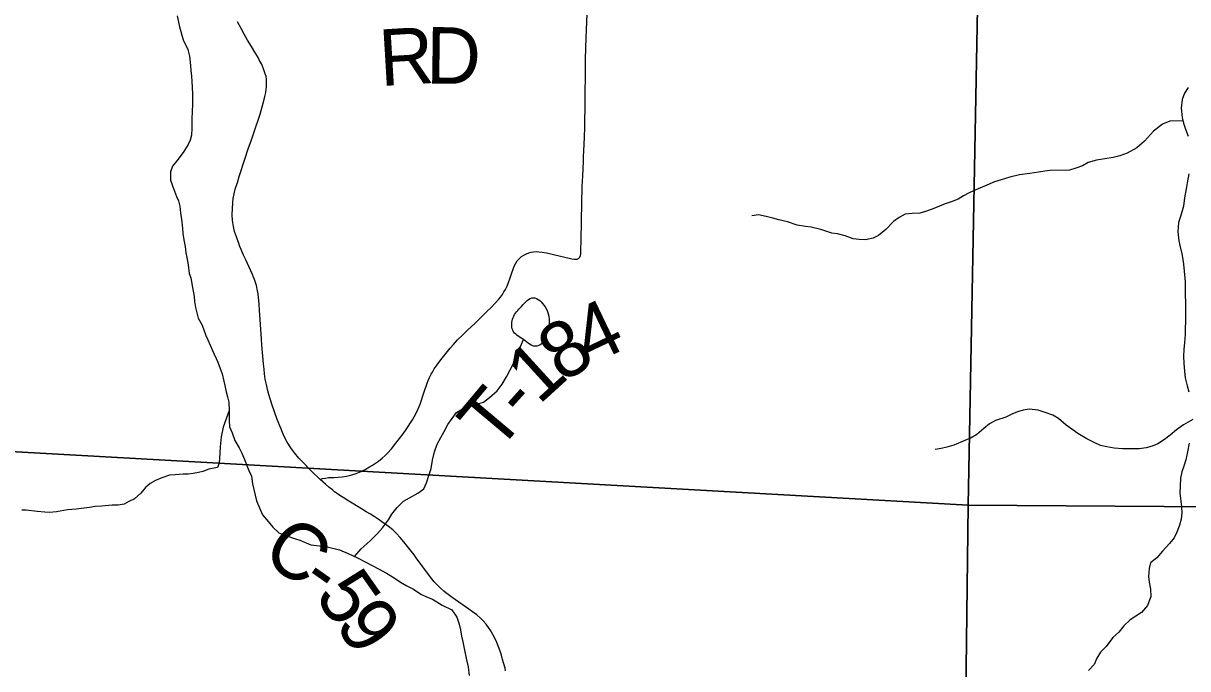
# Model space of a CAD drawing. Extents: x 0 to 34, y 0 to 22.
# Drawn here: x 14.532 to 15.702, y 16.764 to 17.412 of the extents above; entities that cross this region are included whole.
import ezdxf

# ---------------------------------------------------------------- set-up
doc = ezdxf.new("R2010")
doc.units = 0
for name, color, linetype in [('GM_X_Corporation', 7, 'Continuous'), ('GM_X_County_Road', 7, 'Continuous'), ('GM_X_County_Road_Text', 7, 'Continuous'), ('GM_X_Minor_River', 7, 'Continuous'), ('GM_X_Township_Road', 7, 'Continuous'), ('GM_X_Township_Road_Text', 7, 'Continuous')]:
    doc.layers.add(name, color=color, linetype=linetype)

msp = doc.modelspace()

# ---------------------------------------------------------------- linework, layer by layer
at = {"layer": 'GM_X_Corporation'}
for points in [[(14.4926, 17.9788), (15.5004, 17.9447), (15.4816, 16.9282), (14.4709, 16.9847)], [(15.5004, 17.9447), (16.4906, 17.9114), (16.466, 16.9263), (16.466, 16.9214), (15.4816, 16.9282)], [(14.4709, 16.9847), (15.4816, 16.9282), (15.4691, 15.9163), (14.4583, 15.9623)], [(15.4816, 16.9282), (16.466, 16.9214), (16.4563, 15.9084), (15.4691, 15.9163)]]:
    msp.add_lwpolyline(points, close=True, dxfattribs=at)
at = {"layer": 'GM_X_County_Road'}
msp.add_lwpolyline([(15.0166, 16.7617), (15.0161, 16.7642), (15.0148, 16.7687), (15.0136, 16.773), (15.0124, 16.7773), (15.0111, 16.7813), (15.0095, 16.7856), (15.0077, 16.7901), (15.0061, 16.7937), (15.004, 16.7979), (15.0018, 16.8016), (14.9994, 16.8052), (14.997, 16.8085), (14.9942, 16.8117), (14.9914, 16.8146), (14.9878, 16.8177), (14.9835, 16.8209), (14.9797, 16.8236), (14.9629, 16.8353), (14.9589, 16.8381), (14.9566, 16.84), (14.9545, 16.8416), (14.9508, 16.8449), (14.9474, 16.8482), (14.9449, 16.851), (14.9424, 16.8539), (14.9401, 16.857), (14.9269, 16.8751), (14.9248, 16.8781), (14.918, 16.8865), (14.9143, 16.8912), (14.9107, 16.8956), (14.907, 16.8995), (14.9032, 16.9031), (14.8991, 16.9065), (14.8958, 16.9089), (14.8923, 16.9114), (14.8886, 16.914), (14.8847, 16.9166), (14.881, 16.919), (14.8767, 16.9215), (14.8718, 16.9244), (14.8593, 16.9321), (14.8534, 16.9357), (14.8501, 16.9379), (14.8479, 16.9394), (14.8448, 16.9416), (14.8426, 16.9433), (14.8392, 16.9461), (14.8357, 16.9491), (14.8304, 16.954), (14.828, 16.9561), (14.8244, 16.9595), (14.8207, 16.9632), (14.8134, 16.971), (14.8088, 16.9754), (14.8044, 16.9805), (14.8007, 16.9855), (14.7971, 16.9914), (14.7944, 16.9965), (14.7925, 17.0011), (14.7907, 17.0053), (14.7872, 17.0141), (14.7818, 17.0295), (14.7786, 17.0393), (14.7774, 17.0443), (14.7763, 17.0492), (14.7752, 17.0548), (14.7744, 17.0599), (14.7739, 17.0646), (14.7734, 17.0702), (14.7717, 17.0893), (14.7713, 17.0951), (14.7693, 17.1239), (14.7691, 17.1302), (14.7688, 17.1338), (14.7684, 17.1367), (14.7679, 17.1405), (14.7673, 17.1436), (14.7662, 17.1489), (14.7653, 17.1518), (14.7643, 17.1548), (14.7632, 17.1573), (14.7622, 17.16), (14.7555, 17.1745), (14.7534, 17.1794), (14.751, 17.1849), (14.7497, 17.1879), (14.7485, 17.1912), (14.7462, 17.1979), (14.7444, 17.203), (14.7433, 17.208), (14.7424, 17.2141), (14.7419, 17.2199), (14.7425, 17.2323), (14.743, 17.2363), (14.7438, 17.2409), (14.745, 17.2457), (14.7471, 17.2525), (14.749, 17.2585), (14.7545, 17.2757), (14.7579, 17.2861), (14.7612, 17.2953), (14.7642, 17.3043), (14.77, 17.3211), (14.773, 17.3321), (14.7737, 17.3345), (14.7747, 17.3387), (14.7756, 17.3427), (14.7762, 17.346), (14.7763, 17.348), (14.7765, 17.3506), (14.7763, 17.3562), (14.7759, 17.3588), (14.7752, 17.3616), (14.7745, 17.3637), (14.7735, 17.3666), (14.7725, 17.3694), (14.7714, 17.3715), (14.7695, 17.375), (14.7679, 17.3781), (14.7647, 17.3833), (14.7612, 17.3889), (14.7574, 17.3953), (14.7541, 17.4013), (14.7509, 17.4072), (14.7472, 17.4139)], dxfattribs=at)
at = {"layer": 'GM_X_Minor_River'}
for points in [[(14.6867, 17.4199), (14.689, 17.4089), (14.6928, 17.3956), (14.6974, 17.3861), (14.6989, 17.3793), (14.7001, 17.3698), (14.7005, 17.3648), (14.7009, 17.3591), (14.7013, 17.3538), (14.7017, 17.3481), (14.7021, 17.3409), (14.7021, 17.331), (14.7014, 17.3162), (14.7015, 17.3067), (14.7011, 17.2999), (14.6996, 17.295), (14.6977, 17.2904), (14.6928, 17.2824), (14.6864, 17.274), (14.6819, 17.2687), (14.68, 17.263), (14.68, 17.2547), (14.6831, 17.2463), (14.6861, 17.2384), (14.6881, 17.2338), (14.6892, 17.2285), (14.69, 17.2217)], [(15.7025, 17.3478), (15.6988, 17.3421), (15.6966, 17.3356), (15.6956, 17.3272), (15.6965, 17.3177), (15.6978, 17.312), (15.6998, 17.306), (15.7025, 17.2988)], [(15.6973, 17.3143), (15.6841, 17.3141), (15.6769, 17.3109), (15.6676, 17.3039), (15.6587, 17.2939), (15.6508, 17.2873), (15.6414, 17.2818), (15.6339, 17.279), (15.6271, 17.2774), (15.6105, 17.2748), (15.6022, 17.2724), (15.5962, 17.2692), (15.5898, 17.2669), (15.5834, 17.2648), (15.564, 17.2645), (15.5584, 17.2637), (15.5523, 17.2628), (15.5436, 17.2615), (15.533, 17.2602), (15.5232, 17.2577), (15.5145, 17.2549), (15.5081, 17.2529), (15.498, 17.2485), (15.4893, 17.245), (15.4825, 17.2418), (15.4769, 17.2391), (15.4713, 17.2355), (15.4653, 17.2332), (15.4585, 17.2308), (15.4528, 17.2284), (15.4453, 17.2256), (15.4385, 17.2232), (15.4329, 17.2216), (15.4253, 17.2211), (15.4181, 17.2206), (15.4121, 17.217), (15.4065, 17.2132), (15.3986, 17.205), (15.3915, 17.1992), (15.3859, 17.1965), (15.3783, 17.1948), (15.3719, 17.1951), (15.3658, 17.1957), (15.3578, 17.1986), (15.3502, 17.2008), (15.3445, 17.2014), (15.3334, 17.205), (15.3236, 17.2075), (15.3179, 17.2082), (15.3095, 17.2096), (15.3, 17.2128), (15.2912, 17.2149), (15.2851, 17.2164), (15.2786, 17.2182), (15.2707, 17.2199), (15.2642, 17.2187)], [(15.7032, 17.2612), (15.7014, 17.2521), (15.7004, 17.246), (15.6987, 17.2368), (15.6977, 17.2285), (15.6948, 17.2182), (15.6927, 17.212), (15.6921, 17.2029), (15.6933, 17.1938), (15.6946, 17.1878), (15.6962, 17.1806), (15.6975, 17.173), (15.6983, 17.1669), (15.6994, 17.1525), (15.6999, 17.1187), (15.6995, 17.0997), (15.6989, 17.0914), (15.6982, 17.0845), (15.698, 17.0777), (15.6981, 17.0708), (15.699, 17.0625), (15.6995, 17.056), (15.7015, 17.0481), (15.7031, 17.042)], [(14.69, 17.2217), (14.6912, 17.2129), (14.692, 17.2061), (14.6923, 17.2012), (14.6935, 17.1947), (14.6947, 17.1879), (14.6955, 17.1818), (14.6962, 17.1769), (14.6978, 17.1696), (14.6986, 17.1609), (14.7005, 17.1564), (14.702, 17.1469), (14.7036, 17.1378), (14.704, 17.1328), (14.7051, 17.1267), (14.7063, 17.1214), (14.7078, 17.1161), (14.7117, 17.1089), (14.7155, 17.0987), (14.7174, 17.0941), (14.722, 17.0835), (14.7274, 17.0717), (14.73, 17.0653), (14.7319, 17.06), (14.7335, 17.0528), (14.7346, 17.0482), (14.7358, 17.0418), (14.7373, 17.0368), (14.7385, 17.0315), (14.7389, 17.0232), (14.7389, 17.0133), (14.7393, 17.0068), (14.742, 17.0008), (14.7447, 16.9932), (14.7489, 16.9856), (14.7516, 16.9803), (14.7543, 16.9738), (14.7585, 16.9628), (14.7612, 16.9571), (14.7623, 16.9495), (14.7662, 16.9324), (14.7692, 16.9252), (14.7723, 16.9184), (14.778, 16.9116), (14.7826, 16.9059), (14.7887, 16.9002), (14.7948, 16.8979), (14.8054, 16.8942), (14.81, 16.893)], [(14.8649, 16.8766), (14.8716, 16.884), (14.8805, 16.8922), (14.888, 16.8995), (14.8928, 16.9053), (14.8991, 16.9134), (14.9024, 16.9191), (14.9076, 16.9257), (14.914, 16.9322), (14.92, 16.9354), (14.9286, 16.9401), (14.9346, 16.9444), (14.9371, 16.9505), (14.94, 16.9589), (14.9418, 16.965), (14.9432, 16.9734), (14.9453, 16.9818), (14.9479, 16.9894), (14.9515, 16.9959), (14.9548, 17.0021), (14.9585, 17.009), (14.9674, 17.0213), (14.9734, 17.0248), (14.9813, 17.0276), (14.9873, 17.0296), (14.9945, 17.0316), (15.0005, 17.0363), (15.0083, 17.0429), (15.0132, 17.0498), (15.0176, 17.0571), (15.0213, 17.064), (15.0246, 17.0705), (15.0271, 17.0763), (15.0348, 17.0946)], [(14.7389, 17.0232), (14.7329, 17.0064), (14.7307, 16.9966), (14.7299, 16.9867), (14.7296, 16.9802), (14.7288, 16.9704), (14.727, 16.9658), (14.7186, 16.9643), (14.7125, 16.962), (14.708, 16.9608), (14.7027, 16.9597), (14.6978, 16.9593), (14.6928, 16.9593), (14.6845, 16.9585), (14.6788, 16.9581), (14.6712, 16.9554), (14.6647, 16.9528), (14.6594, 16.9497), (14.6549, 16.9459), (14.65, 16.9402), (14.6439, 16.9345), (14.6382, 16.9318), (14.6333, 16.9292), (14.6272, 16.928), (14.6212, 16.928), (14.6109, 16.9272), (14.6041, 16.9268), (14.5984, 16.9257), (14.5851, 16.9241), (14.5764, 16.9234), (14.5654, 16.9214), (14.5582, 16.9207), (14.5536, 16.921), (14.546, 16.9218), (14.535, 16.9229), (14.5304, 16.9229)], [(15.7072, 17.014), (15.698, 17.0089), (15.6909, 17.0038), (15.6845, 16.9984), (15.6789, 16.9941), (15.6722, 16.9898), (15.6662, 16.9875), (15.6605, 16.9855), (15.6533, 16.9846), (15.6438, 16.9848), (15.6366, 16.9847), (15.6283, 16.9853), (15.6207, 16.9867), (15.6146, 16.9881), (15.6081, 16.991), (15.6008, 16.9947), (15.5916, 17.0002), (15.5855, 17.0043), (15.5798, 17.0084), (15.5724, 17.0151), (15.5667, 17.0184), (15.5587, 17.0213), (15.5518, 17.0235), (15.5427, 17.0244), (15.5367, 17.0236), (15.531, 17.022), (15.5254, 17.0196), (15.5194, 17.0164), (15.5088, 17.0132), (15.5028, 17.0097), (15.4972, 17.005), (15.4901, 16.9992), (15.4845, 16.9957), (15.4781, 16.9929), (15.4671, 16.9882), (15.46, 16.9862), (15.4543, 16.9849), (15.4483, 16.9841)], [(15.7036, 16.9904), (15.7019, 16.9816), (15.7001, 16.9736), (15.6983, 16.9671), (15.6962, 16.9614), (15.6947, 16.9553), (15.6945, 16.9473), (15.6943, 16.9401), (15.6951, 16.9321), (15.696, 16.9264), (15.6961, 16.9204), (15.6955, 16.9139), (15.6937, 16.9078), (15.6911, 16.9009), (15.6886, 16.8952), (15.6837, 16.8894), (15.6767, 16.8817), (15.6711, 16.8751), (15.6647, 16.8701), (15.6633, 16.8643), (15.6627, 16.8564), (15.6632, 16.8507), (15.6648, 16.8435), (15.6649, 16.8363), (15.6617, 16.8271), (15.6557, 16.8201), (15.6441, 16.8127), (15.6378, 16.8069), (15.6329, 16.8004), (15.627, 16.795), (15.6203, 16.7861), (15.6143, 16.7803), (15.6107, 16.7742), (15.6081, 16.768), (15.6025, 16.7619)], [(14.81, 16.893), (14.8211, 16.8881), (14.8298, 16.8871), (14.8374, 16.8861), (14.8496, 16.8833), (14.8584, 16.8796), (14.8679, 16.8752), (14.8756, 16.8712), (14.8825, 16.8675), (14.889, 16.8642), (14.897, 16.8598), (14.9047, 16.855), (14.9112, 16.8505), (14.9173, 16.8468), (14.9242, 16.8435), (14.9315, 16.8387), (14.9372, 16.8358), (14.9433, 16.8336), (14.9529, 16.8277), (14.9628, 16.8229), (14.9675, 16.8154), (14.9699, 16.8086), (14.9715, 16.8029), (14.9724, 16.7965), (14.9736, 16.7908), (14.9749, 16.784), (14.9773, 16.7727), (14.979, 16.7655), (14.9802, 16.7568)]]:
    msp.add_lwpolyline(points, dxfattribs=at)
for points in [[(15.0348, 17.0946), (15.0238, 17.1039), (15.0242, 17.1165), (15.0326, 17.1278), (15.0445, 17.1365), (15.0563, 17.1274), (15.06, 17.1179), (15.0596, 17.1053), (15.0523, 17.0898)], [(15.0523, 17.0898), (15.0481, 17.0879), (15.0348, 17.0946)]]:
    msp.add_spline(points, degree=3, dxfattribs=at)
at = {"layer": 'GM_X_Township_Road'}
for points in [[(15.0922, 17.1816), (15.0924, 17.1846), (15.0927, 17.1939), (15.093, 17.2143), (15.0937, 17.2482), (15.0942, 17.2591), (15.0948, 17.2735), (15.0951, 17.2787), (15.0954, 17.284), (15.0957, 17.2908), (15.0959, 17.2978), (15.0962, 17.308), (15.0964, 17.3174), (15.0965, 17.3243), (15.0967, 17.339), (15.0968, 17.3625), (15.0971, 17.3767), (15.0977, 17.3976), (15.0989, 17.4295)], [(14.8304, 16.954), (14.8328, 16.9547), (14.8356, 16.9553), (14.8387, 16.9557), (14.8416, 16.9558), (14.8442, 16.9559), (14.8485, 16.9561), (14.8526, 16.9565), (14.8567, 16.9572), (14.862, 16.9585), (14.8665, 16.96), (14.8715, 16.962), (14.8755, 16.964), (14.88, 16.9665), (14.883, 16.9683), (14.8889, 16.9723), (14.8926, 16.9752), (14.8956, 16.9778), (14.8984, 16.9806), (14.9021, 16.9848), (14.9065, 16.9903), (14.9138, 16.9999), (14.9169, 17.0042), (14.9232, 17.0138), (14.9249, 17.0168), (14.9269, 17.0206), (14.9288, 17.0247), (14.9307, 17.0296), (14.9344, 17.0408), (14.9379, 17.0507), (14.939, 17.0534), (14.9402, 17.0564), (14.9419, 17.0597), (14.9431, 17.0618), (14.945, 17.065), (14.9478, 17.0691), (14.9515, 17.0741), (14.961, 17.0858), (14.9643, 17.0896), (14.9684, 17.0941), (14.9733, 17.099), (14.9785, 17.104), (14.9861, 17.1111), (14.9976, 17.1222), (15.0025, 17.1271), (15.0097, 17.135), (15.0114, 17.1371), (15.0135, 17.1399), (15.015, 17.1423), (15.0165, 17.1448), (15.0181, 17.1482), (15.0197, 17.152), (15.0212, 17.1564), (15.023, 17.1617), (15.0241, 17.1653), (15.0253, 17.1684), (15.0268, 17.1714), (15.0282, 17.1736), (15.0295, 17.1751), (15.0312, 17.1767), (15.0327, 17.178), (15.0349, 17.1794), (15.0375, 17.1807), (15.0399, 17.1816), (15.0423, 17.1823), (15.0446, 17.1827), (15.0474, 17.1829), (15.05, 17.1828), (15.0533, 17.1824), (15.0578, 17.1817), (15.0635, 17.1804), (15.0833, 17.1757), (15.0856, 17.1753), (15.0875, 17.1752), (15.0886, 17.1753), (15.0899, 17.1758), (15.0906, 17.1765), (15.0912, 17.1774), (15.0918, 17.179), (15.0921, 17.1806), (15.0922, 17.1816)]]:
    msp.add_lwpolyline(points, dxfattribs=at)

# ---------------------------------------------------------------- texts
at = {"layer": 'GM_X_County_Road_Text'}
for s, rotation, p in [('C', 322.9935, (14.7694, 16.8761)), ('-', 325.0287, (14.8085, 16.8467)), ('5', 305.1003, (14.8239, 16.837)), ('9', 305.4215, (14.8442, 16.808))]:
    msp.add_text(s, height=0.0568, rotation=rotation, dxfattribs=at).set_placement(p)
at = {"layer": 'GM_X_Township_Road_Text'}
for s, rotation, p in [('R', 3.4054, (14.8911, 17.3492)), ('D', 359.2241, (14.9366, 17.3519)), ('4', 25.5177, (15.1016, 17.0682)), ('8', 32.9829, (15.0739, 17.0501)), ('1', 42.3496, (15.05, 17.0281)), ('T', 49.9184, (15.0084, 16.9796)), ('-', 47.9931, (15.0354, 17.0118))]:
    msp.add_text(s, height=0.0568, rotation=rotation, dxfattribs=at).set_placement(p)

doc.saveas('drawing.dxf')
